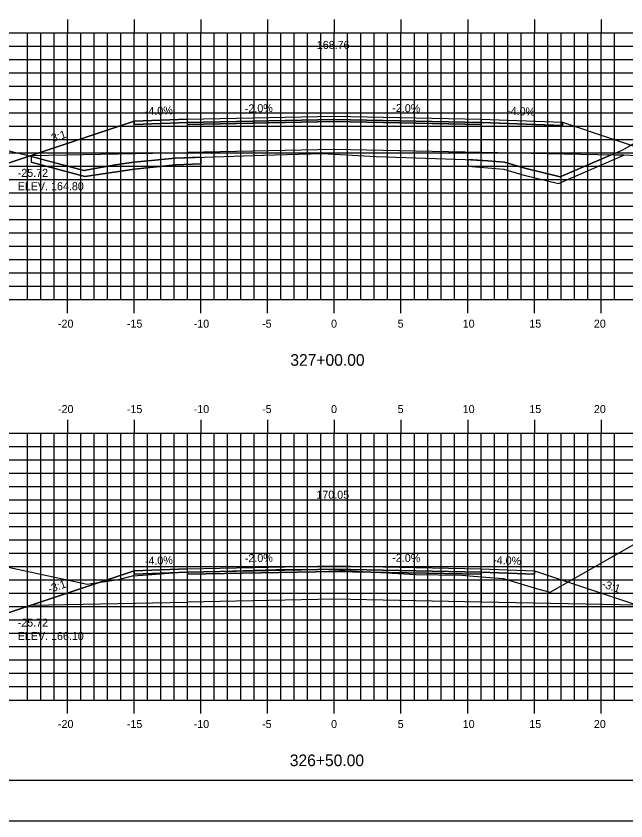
# Model space of a CAD drawing. Extents: x 1140759 to 1140929, y 608981 to 609091.
# Drawn here: x 1140818.2 to 1140863.9, y 608981.3 to 609041.6 of the extents above; entities that cross this region are included whole.
import ezdxf

# ---------------------------------------------------------------- set-up
doc = ezdxf.new("R2010")
doc.units = 0
for name, color, linetype in [('ANNOTATION', 7, 'Continuous'), ('BORDER', 7, 'Continuous'), ('D_Roadway_Centerline', 7, 'Continuous'), ('D_Roadway_Centerline_Text', 7, 'Continuous'), ('D_Roadway_Edge_Shoulder', 7, 'Continuous'), ('D_Roadway_Edge_TW', 7, 'Continuous'), ('D_Roadway_Pavement', 7, 'Continuous'), ('D_Roadway_SlopeLines', 7, 'Continuous'), ('D_Roadway_SubGrade', 7, 'Continuous'), ('D_Text_Standard', 7, 'Continuous'), ('H_V ANNOTATION', 7, 'Continuous'), ('MAJOR', 7, 'Continuous'), ('MINOR', 7, 'Continuous'), ('PLOT BOUNDARY', 7, 'Continuous'), ('S_Roadway_Centerline', 7, 'Continuous'), ('SHADING', 7, 'Continuous')]:
    doc.layers.add(name, color=color, linetype=linetype)

msp = doc.modelspace()

# ---------------------------------------------------------------- linework, layer by layer
for points in [[(1140810.883, 609031.567), (1140812.133, 609031.496), (1140813.383, 609031.267), (1140814.633, 609030.879), (1140815.883, 609030.333), (1140816.276, 609030.136), (1140819.276, 609031.136), (1140827, 609033.711), (1140827.001, 609033.711), (1140831.001, 609033.871), (1140842.001, 609034.091), (1140853.001, 609033.871), (1140859.098, 609033.627), (1140866.688, 609031.097), (1140869.688, 609030.097), (1140875.149, 609032.828), (1140876.399, 609033.379), (1140877.649, 609033.781), (1140878.899, 609034.035), (1140880.149, 609034.141)], [(1140806.654, 608999.652), (1140807.904, 608999.725), (1140809.154, 608999.598), (1140810.404, 608999.272), (1140811.654, 608998.747), (1140816.276, 608996.435), (1140819.276, 608997.435), (1140827, 609000.01), (1140827.001, 609000.01), (1140831.001, 609000.17), (1140842.001, 609000.39), (1140853.001, 609000.17), (1140857.001, 609000.01), (1140864.725, 608997.435), (1140867.725, 608996.435), (1140882.606, 609003.876), (1140883.856, 609004.435), (1140885.106, 609004.861), (1140886.356, 609005.154), (1140887.606, 609005.314)]]:
    msp.add_lwpolyline(points)
at = {"layer": 'BORDER'}
msp.add_lwpolyline([(1140767.001, 608984.335), (1140927.001, 608984.335), (1140927.001, 609089.335), (1140767.001, 609089.335)], close=True, dxfattribs=at)
at = {"layer": 'D_Roadway_Edge_Shoulder'}
for points in [[(1140831.001, 609033.871), (1140827.001, 609033.711), (1140827.001, 609033.461), (1140831.001, 609033.621)], [(1140853.001, 609033.871), (1140859.098, 609033.627), (1140859.098, 609033.377), (1140853.001, 609033.621)], [(1140831.001, 609000.17), (1140827.001, 609000.01), (1140827.001, 608999.76), (1140831.001, 608999.92)], [(1140853.001, 609000.17), (1140857.001, 609000.01), (1140857.001, 608999.76), (1140853.001, 608999.92)]]:
    msp.add_lwpolyline(points, close=True, dxfattribs=at)
at = {"layer": 'D_Roadway_Edge_TW'}
for points in [[(1140831.001, 609033.621), (1140831.001, 609033.871), (1140842.001, 609034.091), (1140853.001, 609033.871), (1140853.001, 609033.621), (1140842.001, 609033.841)], [(1140831.001, 608999.92), (1140831.001, 609000.17), (1140842.001, 609000.39), (1140853.001, 609000.17), (1140853.001, 608999.92), (1140842.001, 609000.14)]]:
    msp.add_lwpolyline(points, close=True, dxfattribs=at)
at = {"layer": 'D_Roadway_Pavement'}
for points in [[(1140831.001, 609033.454), (1140831.001, 609033.621), (1140842.001, 609033.841), (1140853.001, 609033.621), (1140853.001, 609033.454), (1140842.001, 609033.674)], [(1140831.001, 608999.753), (1140831.001, 608999.92), (1140842.001, 609000.14), (1140853.001, 608999.92), (1140853.001, 608999.753), (1140842.001, 608999.973)]]:
    msp.add_lwpolyline(points, close=True, dxfattribs=at)
at = {"layer": 'D_Roadway_SlopeLines'}
msp.add_line((1140819.276, 609031.059), (1140819.276, 609030.63), dxfattribs=at)
for points in [[(1140819.276, 609031.136), (1140816.276, 609030.136)], [(1140832.001, 609031), (1140832.001, 609030.5), (1140830.104, 609030.439), (1140827.039, 609030.116), (1140823.306, 609029.56), (1140819.276, 609030.63)], [(1140852.001, 609030.829), (1140852.001, 609030.329), (1140854.715, 609030.122), (1140856.127, 609029.698), (1140858.8, 609029.047), (1140863.71, 609031.156)], [(1140819.276, 608997.435), (1140816.276, 608996.435)]]:
    msp.add_lwpolyline(points, dxfattribs=at)
at = {"layer": 'D_Roadway_SubGrade'}
for points in [[(1140831.001, 609033.454), (1140831.001, 609033.621), (1140827.001, 609033.461), (1140827.001, 609033.711), (1140827, 609033.711), (1140819.276, 609031.136), (1140831.001, 609031.371)], [(1140831.001, 609031.371), (1140831.001, 609033.454), (1140842.001, 609033.674), (1140853.001, 609033.454), (1140853.001, 609031.371), (1140842.001, 609031.591)], [(1140853.001, 609033.454), (1140853.001, 609033.621), (1140859.098, 609033.377), (1140859.098, 609033.627), (1140859.098, 609033.627), (1140866.688, 609031.097), (1140853.001, 609031.371)], [(1140831.001, 608999.753), (1140831.001, 608999.92), (1140827.001, 608999.76), (1140827.001, 609000.01), (1140827, 609000.01), (1140819.276, 608997.435), (1140831.001, 608997.67)], [(1140831.001, 608997.67), (1140831.001, 608999.753), (1140842.001, 608999.973), (1140853.001, 608999.753), (1140853.001, 608997.67), (1140842.001, 608997.89)], [(1140853.001, 608999.753), (1140853.001, 608999.92), (1140857.001, 608999.76), (1140857.001, 609000.01), (1140857.001, 609000.01), (1140864.725, 608997.435), (1140853.001, 608997.67)]]:
    msp.add_lwpolyline(points, close=True, dxfattribs=at)
at = {"layer": 'MAJOR'}
for p, q in [((1140822.001, 609041.337), (1140822.001, 609040.335)), ((1140827.001, 609041.337), (1140827.001, 609040.335)), ((1140832.001, 609041.337), (1140832.001, 609040.335)), ((1140837.001, 609041.337), (1140837.001, 609040.335)), ((1140842.001, 609041.337), (1140842.001, 609040.335)), ((1140847.001, 609041.337), (1140847.001, 609040.335)), ((1140852.001, 609041.337), (1140852.001, 609040.335)), ((1140857.001, 609041.337), (1140857.001, 609040.335)), ((1140862.001, 609041.337), (1140862.001, 609040.335)), ((1140772.001, 609040.335), (1140912.001, 609040.335)), ((1140772.001, 609040.335), (1140912.001, 609040.335)), ((1140822.001, 609020.335), (1140822.001, 609040.335)), ((1140827.001, 609020.335), (1140827.001, 609040.335)), ((1140832.001, 609020.335), (1140832.001, 609040.335)), ((1140837.001, 609020.335), (1140837.001, 609040.335)), ((1140842.001, 609020.335), (1140842.001, 609040.335)), ((1140847.001, 609020.335), (1140847.001, 609040.335)), ((1140852.001, 609020.335), (1140852.001, 609040.335)), ((1140857.001, 609020.335), (1140857.001, 609040.335)), ((1140862.001, 609020.335), (1140862.001, 609040.335)), ((1140772.001, 609035.335), (1140912.001, 609035.335)), ((1140772.001, 609030.335), (1140912.001, 609030.335)), ((1140772.001, 609025.335), (1140912.001, 609025.335)), ((1140772.001, 609020.335), (1140912.001, 609020.335)), ((1140772.001, 609020.335), (1140912.001, 609020.335)), ((1140822.001, 609019.333), (1140822.001, 609020.335)), ((1140827.001, 609019.333), (1140827.001, 609020.335)), ((1140832.001, 609019.333), (1140832.001, 609020.335)), ((1140837.001, 609019.333), (1140837.001, 609020.335)), ((1140842.001, 609019.333), (1140842.001, 609020.335)), ((1140847.001, 609019.333), (1140847.001, 609020.335)), ((1140852.001, 609019.333), (1140852.001, 609020.335)), ((1140857.001, 609019.333), (1140857.001, 609020.335)), ((1140862.001, 609019.333), (1140862.001, 609020.335)), ((1140822.001, 609011.337), (1140822.001, 609010.335)), ((1140827.001, 609011.337), (1140827.001, 609010.335)), ((1140832.001, 609011.337), (1140832.001, 609010.335)), ((1140837.001, 609011.337), (1140837.001, 609010.335)), ((1140842.001, 609011.337), (1140842.001, 609010.335)), ((1140847.001, 609011.337), (1140847.001, 609010.335)), ((1140852.001, 609011.337), (1140852.001, 609010.335)), ((1140857.001, 609011.337), (1140857.001, 609010.335)), ((1140862.001, 609011.337), (1140862.001, 609010.335)), ((1140772.001, 609010.335), (1140912.001, 609010.335)), ((1140772.001, 609010.335), (1140912.001, 609010.335)), ((1140822.001, 608990.335), (1140822.001, 609010.335)), ((1140827.001, 608990.335), (1140827.001, 609010.335)), ((1140832.001, 608990.335), (1140832.001, 609010.335)), ((1140837.001, 608990.335), (1140837.001, 609010.335)), ((1140842.001, 608990.335), (1140842.001, 609010.335)), ((1140847.001, 608990.335), (1140847.001, 609010.335)), ((1140852.001, 608990.335), (1140852.001, 609010.335)), ((1140857.001, 608990.335), (1140857.001, 609010.335)), ((1140862.001, 608990.335), (1140862.001, 609010.335)), ((1140772.001, 609005.335), (1140912.001, 609005.335)), ((1140772.001, 609000.335), (1140912.001, 609000.335)), ((1140772.001, 608995.335), (1140912.001, 608995.335)), ((1140772.001, 608990.335), (1140912.001, 608990.335)), ((1140772.001, 608990.335), (1140912.001, 608990.335)), ((1140822.001, 608989.333), (1140822.001, 608990.335)), ((1140827.001, 608989.333), (1140827.001, 608990.335)), ((1140832.001, 608989.333), (1140832.001, 608990.335)), ((1140837.001, 608989.333), (1140837.001, 608990.335)), ((1140842.001, 608989.333), (1140842.001, 608990.335)), ((1140847.001, 608989.333), (1140847.001, 608990.335)), ((1140852.001, 608989.333), (1140852.001, 608990.335)), ((1140857.001, 608989.333), (1140857.001, 608990.335)), ((1140862.001, 608989.333), (1140862.001, 608990.335))]:
    msp.add_line(p, q, dxfattribs=at)
at = {"layer": 'MINOR'}
for p, q in [((1140819.001, 609020.335), (1140819.001, 609040.335)), ((1140820.001, 609020.335), (1140820.001, 609040.335)), ((1140821.001, 609020.335), (1140821.001, 609040.335)), ((1140823.001, 609020.335), (1140823.001, 609040.335)), ((1140824.001, 609020.335), (1140824.001, 609040.335)), ((1140825.001, 609020.335), (1140825.001, 609040.335)), ((1140826.001, 609020.335), (1140826.001, 609040.335)), ((1140828.001, 609020.335), (1140828.001, 609040.335)), ((1140829.001, 609020.335), (1140829.001, 609040.335)), ((1140830.001, 609020.335), (1140830.001, 609040.335)), ((1140831.001, 609020.335), (1140831.001, 609040.335)), ((1140833.001, 609020.335), (1140833.001, 609040.335)), ((1140834.001, 609020.335), (1140834.001, 609040.335)), ((1140835.001, 609020.335), (1140835.001, 609040.335)), ((1140836.001, 609020.335), (1140836.001, 609040.335)), ((1140838.001, 609020.335), (1140838.001, 609040.335)), ((1140839.001, 609020.335), (1140839.001, 609040.335)), ((1140840.001, 609020.335), (1140840.001, 609040.335)), ((1140841.001, 609020.335), (1140841.001, 609040.335)), ((1140843.001, 609020.335), (1140843.001, 609040.335)), ((1140844.001, 609020.335), (1140844.001, 609040.335)), ((1140845.001, 609020.335), (1140845.001, 609040.335)), ((1140846.001, 609020.335), (1140846.001, 609040.335)), ((1140848.001, 609020.335), (1140848.001, 609040.335)), ((1140849.001, 609020.335), (1140849.001, 609040.335)), ((1140850.001, 609020.335), (1140850.001, 609040.335)), ((1140851.001, 609020.335), (1140851.001, 609040.335)), ((1140853.001, 609020.335), (1140853.001, 609040.335)), ((1140854.001, 609020.335), (1140854.001, 609040.335)), ((1140855.001, 609020.335), (1140855.001, 609040.335)), ((1140856.001, 609020.335), (1140856.001, 609040.335)), ((1140858.001, 609020.335), (1140858.001, 609040.335)), ((1140859.001, 609020.335), (1140859.001, 609040.335)), ((1140860.001, 609020.335), (1140860.001, 609040.335)), ((1140861.001, 609020.335), (1140861.001, 609040.335)), ((1140863.001, 609020.335), (1140863.001, 609040.335)), ((1140772.001, 609039.335), (1140912.001, 609039.335)), ((1140772.001, 609038.335), (1140912.001, 609038.335)), ((1140772.001, 609037.335), (1140912.001, 609037.335)), ((1140772.001, 609036.335), (1140912.001, 609036.335)), ((1140772.001, 609034.335), (1140912.001, 609034.335)), ((1140772.001, 609033.335), (1140912.001, 609033.335)), ((1140772.001, 609032.335), (1140912.001, 609032.335)), ((1140772.001, 609031.335), (1140912.001, 609031.335)), ((1140772.001, 609029.335), (1140912.001, 609029.335)), ((1140772.001, 609028.335), (1140912.001, 609028.335)), ((1140772.001, 609027.335), (1140912.001, 609027.335)), ((1140772.001, 609026.335), (1140912.001, 609026.335)), ((1140772.001, 609024.335), (1140912.001, 609024.335)), ((1140772.001, 609023.335), (1140912.001, 609023.335)), ((1140772.001, 609022.335), (1140912.001, 609022.335)), ((1140772.001, 609021.335), (1140912.001, 609021.335)), ((1140819.001, 608990.335), (1140819.001, 609010.335)), ((1140820.001, 608990.335), (1140820.001, 609010.335)), ((1140821.001, 608990.335), (1140821.001, 609010.335)), ((1140823.001, 608990.335), (1140823.001, 609010.335)), ((1140824.001, 608990.335), (1140824.001, 609010.335)), ((1140825.001, 608990.335), (1140825.001, 609010.335)), ((1140826.001, 608990.335), (1140826.001, 609010.335)), ((1140828.001, 608990.335), (1140828.001, 609010.335)), ((1140829.001, 608990.335), (1140829.001, 609010.335)), ((1140830.001, 608990.335), (1140830.001, 609010.335)), ((1140831.001, 608990.335), (1140831.001, 609010.335)), ((1140833.001, 608990.335), (1140833.001, 609010.335)), ((1140834.001, 608990.335), (1140834.001, 609010.335)), ((1140835.001, 608990.335), (1140835.001, 609010.335)), ((1140836.001, 608990.335), (1140836.001, 609010.335)), ((1140838.001, 608990.335), (1140838.001, 609010.335)), ((1140839.001, 608990.335), (1140839.001, 609010.335)), ((1140840.001, 608990.335), (1140840.001, 609010.335)), ((1140841.001, 608990.335), (1140841.001, 609010.335)), ((1140843.001, 608990.335), (1140843.001, 609010.335)), ((1140844.001, 608990.335), (1140844.001, 609010.335)), ((1140845.001, 608990.335), (1140845.001, 609010.335)), ((1140846.001, 608990.335), (1140846.001, 609010.335)), ((1140848.001, 608990.335), (1140848.001, 609010.335)), ((1140849.001, 608990.335), (1140849.001, 609010.335)), ((1140850.001, 608990.335), (1140850.001, 609010.335)), ((1140851.001, 608990.335), (1140851.001, 609010.335)), ((1140853.001, 608990.335), (1140853.001, 609010.335)), ((1140854.001, 608990.335), (1140854.001, 609010.335)), ((1140855.001, 608990.335), (1140855.001, 609010.335)), ((1140856.001, 608990.335), (1140856.001, 609010.335)), ((1140858.001, 608990.335), (1140858.001, 609010.335)), ((1140859.001, 608990.335), (1140859.001, 609010.335)), ((1140860.001, 608990.335), (1140860.001, 609010.335)), ((1140861.001, 608990.335), (1140861.001, 609010.335)), ((1140863.001, 608990.335), (1140863.001, 609010.335)), ((1140772.001, 609009.335), (1140912.001, 609009.335)), ((1140772.001, 609008.335), (1140912.001, 609008.335)), ((1140772.001, 609007.335), (1140912.001, 609007.335)), ((1140772.001, 609006.335), (1140912.001, 609006.335)), ((1140772.001, 609004.335), (1140912.001, 609004.335)), ((1140772.001, 609003.335), (1140912.001, 609003.335)), ((1140772.001, 609002.335), (1140912.001, 609002.335)), ((1140772.001, 609001.335), (1140912.001, 609001.335)), ((1140772.001, 608999.335), (1140912.001, 608999.335)), ((1140772.001, 608998.335), (1140912.001, 608998.335)), ((1140772.001, 608997.335), (1140912.001, 608997.335)), ((1140772.001, 608996.335), (1140912.001, 608996.335)), ((1140772.001, 608994.335), (1140912.001, 608994.335)), ((1140772.001, 608993.335), (1140912.001, 608993.335)), ((1140772.001, 608992.335), (1140912.001, 608992.335)), ((1140772.001, 608991.335), (1140912.001, 608991.335))]:
    msp.add_line(p, q, dxfattribs=at)
at = {"layer": 'PLOT BOUNDARY'}
msp.add_lwpolyline([(1140758.908, 608981.276), (1140928.908, 608981.276), (1140928.908, 609091.276), (1140758.908, 609091.276)], close=True, dxfattribs=at)
at = {"layer": 'S_Roadway_Centerline'}
for points in [[(1140801.487, 609031.61), (1140807.51, 609031.545), (1140817.109, 609031.607), (1140818.751, 609031.199), (1140823.239, 609030.006), (1140825.606, 609030.431), (1140826.984, 609030.636), (1140828.295, 609030.749), (1140830.088, 609030.938), (1140836.661, 609031.15), (1140841.085, 609031.284), (1140845.133, 609031.054), (1140851.798, 609030.843), (1140853.505, 609030.727), (1140854.754, 609030.632), (1140856.271, 609030.176), (1140858.918, 609029.531), (1140863.578, 609031.533), (1140867.623, 609033.826), (1140881.853, 609034.183), (1140886.58, 609034.308), (1140902.941, 609034.493), (1140912.001, 609034.621)], [(1140801.751, 608998.976), (1140814.306, 609000.707), (1140815.787, 609000.705), (1140816.993, 609000.418), (1140823.481, 608999.018), (1140825.828, 608999.368), (1140826.874, 608999.635), (1140827.996, 608999.704), (1140830.23, 608999.898), (1140837.667, 609000.12), (1140841.075, 609000.147), (1140848.107, 608999.748), (1140851.527, 608999.693), (1140853.662, 608999.523), (1140854.647, 608999.437), (1140857.22, 608998.676), (1140858.176, 608998.42), (1140865.509, 609002.587), (1140868.086, 609003.78), (1140874.07, 609004.299), (1140887.7, 609005.321), (1140893.531, 609005.124), (1140897.997, 609004.657), (1140912.001, 609005.073)]]:
    msp.add_lwpolyline(points, dxfattribs=at)
at = {"layer": 'SHADING'}
for p, q in [((1140819.276, 609031.059), (1140819.276, 609030.63)), ((1140863.71, 609031.156), (1140862.746, 609031.176))]:
    msp.add_line(p, q, dxfattribs=at)
for points in [[(1140832.001, 609031), (1140830.088, 609030.938), (1140828.295, 609030.749), (1140826.984, 609030.636), (1140825.606, 609030.431), (1140823.239, 609030.006), (1140819.276, 609031.059)], [(1140819.276, 609030.63), (1140823.306, 609029.56), (1140827.039, 609030.116), (1140830.104, 609030.439), (1140832.001, 609030.5), (1140832.001, 609031)], [(1140862.746, 609031.176), (1140858.918, 609029.531), (1140856.271, 609030.176), (1140854.754, 609030.632), (1140853.505, 609030.727), (1140852.001, 609030.829)], [(1140852.001, 609030.829), (1140852.001, 609030.329), (1140854.715, 609030.122), (1140856.127, 609029.698), (1140858.8, 609029.047), (1140863.71, 609031.156)]]:
    msp.add_lwpolyline(points, dxfattribs=at)

# ---------------------------------------------------------------- texts
at = {"layer": 'ANNOTATION'}
for s, rotation, p in [('-4.0%', 2.29061, (1140827.817, 609034.144)), ('-2.0%', 1.14576, (1140835.304, 609034.357)), ('-2.0%', 358.85424, (1140846.344, 609034.404)), ('-4.0%', 357.70939, (1140854.945, 609034.194)), ('-3:1', 18.43482, (1140820.655, 609032.05)), ('-4.0%', 2.29061, (1140827.817, 609000.443)), ('-2.0%', 1.14576, (1140835.304, 609000.656)), ('-2.0%', 358.85424, (1140846.344, 609000.703)), ('-4.0%', 357.70939, (1140853.897, 609000.535)), ('-3:1', 18.43482, (1140820.655, 608998.349)), ('-3:1', 341.56521, (1140862.012, 608998.793))]:
    msp.add_text(s, height=0.6, rotation=rotation, dxfattribs=at).set_placement(p)
at = {"layer": 'D_Roadway_Centerline'}
for s, p in [('C', (1140841.996, 609034.091)), ('C', (1140841.996, 609034.091)), ('L', (1140842.001, 609034.083)), ('L', (1140842.001, 609034.083)), ('C', (1140841.996, 609000.39)), ('C', (1140841.996, 609000.39)), ('L', (1140842.001, 609000.383)), ('L', (1140842.001, 609000.383))]:
    msp.add_text(s, height=0.0146, dxfattribs=at).set_placement(p)
at = {"layer": 'D_Roadway_Centerline_Text'}
for s, p in [('168.76', (1140840.69, 609039.123)), ('170.05', (1140840.661, 609005.422))]:
    msp.add_text(s, height=0.6, dxfattribs=at).set_placement(p)
at = {"layer": 'D_Text_Standard'}
for s, p in [('-25.72', (1140818.277, 609029.536)), ('ELEV. 164.80', (1140818.277, 609028.534)), ('-25.72', (1140818.277, 608995.835)), ('ELEV. 166.10', (1140818.277, 608994.833))]:
    msp.add_text(s, height=0.6, dxfattribs=at).set_placement(p)
at = {"layer": 'H_V ANNOTATION'}
for s, height, p in [('-20', 0.6, (1140821.295, 609018.235)), ('-15', 0.6, (1140826.458, 609018.235)), ('-10', 0.6, (1140831.466, 609018.235)), ('-5', 0.6, (1140836.592, 609018.235)), ('0', 0.6, (1140841.76, 609018.235)), ('5', 0.6, (1140846.752, 609018.235)), ('10', 0.6, (1140851.626, 609018.235)), ('15', 0.6, (1140856.618, 609018.235)), ('20', 0.6, (1140861.455, 609018.235)), ('327+00.00', 0.875, (1140838.708, 609015.378)), ('-20', 0.6, (1140821.295, 609011.835)), ('-15', 0.6, (1140826.458, 609011.835)), ('-10', 0.6, (1140831.466, 609011.835)), ('-5', 0.6, (1140836.592, 609011.835)), ('0', 0.6, (1140841.76, 609011.835)), ('5', 0.6, (1140846.752, 609011.835)), ('10', 0.6, (1140851.626, 609011.835)), ('15', 0.6, (1140856.618, 609011.835)), ('20', 0.6, (1140861.455, 609011.835)), ('-20', 0.6, (1140821.295, 608988.235)), ('-15', 0.6, (1140826.458, 608988.235)), ('-10', 0.6, (1140831.466, 608988.235)), ('-5', 0.6, (1140836.592, 608988.235)), ('0', 0.6, (1140841.76, 608988.235)), ('5', 0.6, (1140846.752, 608988.235)), ('10', 0.6, (1140851.626, 608988.235)), ('15', 0.6, (1140856.618, 608988.235)), ('20', 0.6, (1140861.455, 608988.235)), ('326+50.00', 0.875, (1140838.669, 608985.378))]:
    msp.add_text(s, height=height, dxfattribs=at).set_placement(p)
at = {"layer": 'S_Roadway_Centerline'}
for s, p in [('L', (1140841.076, 609031.277)), ('C', (1140841.079, 609031.284)), ('L', (1140841.066, 609000.139)), ('C', (1140841.07, 609000.147))]:
    msp.add_text(s, height=0.0146, dxfattribs=at).set_placement(p)

doc.saveas('drawing.dxf')
